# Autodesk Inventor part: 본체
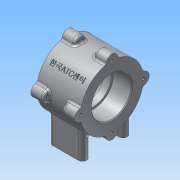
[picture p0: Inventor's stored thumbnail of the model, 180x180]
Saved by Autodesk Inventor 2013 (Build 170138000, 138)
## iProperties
Created: 2015-03
Part Number: 본체
Material: 알루미늄 6061
Document SubType Name: Modeling
Designer: Administrator
Density: 2.71 g/cm^3
Mass: 450.744 g
Surface Area: 332.371 cm^2
Volume: 166.326 cm^3
Author: Administrator
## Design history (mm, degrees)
sketch "스케치1"
  geometry: C1 r 37 at (0, 0); 1 further point
  constraints: 1 centre point, 1 coincident
  dimensions: "d0" = 74 diameter of C1
extrude "돌출1" new body sketch "스케치1" stored distance "d1" = 52; taper "d2" = 0 deg
sketch "스케치2"
  geometry: L1 (0, 0)-(0, 37); A1 r 37 centre (0, 0) between (0, 37) and (6.969, 36.338) reference; A2 r 7 centre (0, 37) between (6.969, 36.338) and (-6.969, 36.338)
  constraints: 5 point on circle, 2 end point, 1 centre point, 1 coincident, 1 vertical
  dimensions: "d4" = 14 diameter of A2
extrude "돌출2" join sketch "스케치2" distance "d5" = 15; taper "d6" = 0 deg
hole "구멍1" diameter "d12" = 42; stored, may be unused: countersink angle "d16" = 90 deg, drill point angle "d18" = 0 deg; dims "d10" = 10, "d11" = 10, "d13" = 6, "d14" = 47, "d15" = 22, "d17" = 8
chamfer "모따기1" distance "d19" = 1; stored, may be unused: second distance "d20" = 2, angle "d21" = 45 deg
fillet "모깎기1" dims "d22" = 0.3
fillet "모깎기2" dims "d23" = 3
fillet "모깎기3" dims "d24" = 3
sketch "스케치3"
  geometry: A1 r 7 centre (-37, 0) between (-38.239, 6.889) and (-38.239, -6.889) reference; A2 r 7 centre (0, -37) between (-6.889, -38.239) and (6.889, -38.239) reference; A3 r 7 centre (37, 0) between (38.239, -6.889) and (38.239, 6.889) reference; A4 r 7 centre (0, 37) between (6.889, 38.239) and (-6.889, 38.239) reference; 4 further points
  constraints: 4 coincident
hole "구멍2" sketch "스케치3" at (0, 37), (-37, 0), (37, 0), (0, -37) diameter "d25" = 3.242; stored, may be unused: countersink angle "d29" = 90 deg, drill point angle "d31" = 118 deg; dims "d26" = 8, "d27" = 47, "d28" = 22, "d30" = 11
sketch "스케치4"
  geometry: A1 r 7 centre (-37, 0) between (-38.239, 6.889) and (-38.239, -6.889) reference; A2 r 7 centre (0, -37) between (-6.889, -38.239) and (6.889, -38.239) reference; A3 r 7 centre (37, 0) between (38.239, -6.889) and (38.239, 6.889) reference; A4 r 7 centre (0, 37) between (6.889, 38.239) and (-6.889, 38.239) reference; 4 further points
  constraints: 4 coincident
hole "구멍3" sketch "스케치4" at (0, 37), (-37, 0), (0, -37), (37, 0) diameter "d32" = 3.242; stored, may be unused: countersink angle "d36" = 90 deg, drill point angle "d38" = 118 deg; dims "d33" = 8, "d34" = 47, "d35" = 22, "d37" = 11
node "작업 평면2"
  node "작업 평면1"
sketch "스케치5"
  geometry: 2 further points
  constraints: 1 coincident, 1 other
feature "엠보싱1" sketch "스케치5" dims "d41" = 0.5, "d42" = 0
node "작업 평면3"
sketch "스케치6"
  geometry: L1 (-29, 15)-(-29, -15); L2 (-19, -15)-(-19, 15); A1 r 5 centre (-24, -15) between (-29, -15) and (-19, -15); A2 r 5 centre (-24, 15) between (-19, 15) and (-29, 15); 2 further points
  constraints: 4 end point, 4 point on circle, 4 tangent, 2 centre point, 1 horizontal alignment, 1 midpoint, 1 parallel, 1 vertical
  dimensions: "d44" = 40 dimension on A1 A2; "d46" = 5 radius of A2; "d47" = 24 horizontal distance of A1.centre point (0, 0)
extrude "돌출3" join sketch "스케치6" stored distance "d48" = 15; taper "d49" = 0 deg
sketch "스케치7"
  geometry: L1 (-29, -15)-(-29, 15) reference; L2 (-19, 15)-(-19, -15) reference; L3 (29, 15)-(29, -15) reference; L4 (19, -15)-(19, 15) reference; A1 r 5 centre (-24, 15) between (-19, 15) and (-29, 15) reference; A2 r 5 centre (-24, -15) between (-29, -15) and (-19, -15) reference; A3 r 5 centre (24, -15) between (19, -15) and (29, -15) reference; A4 r 5 centre (24, 15) between (29, 15) and (19, 15) reference; 5 further points
  constraints: 4 coincident
hole "구멍4" sketch "스케치7" at (-24, 15), (-24, -15), (24, -15), (24, 15) diameter "d50" = 4.134; stored, may be unused: countersink angle "d54" = 90 deg, drill point angle "d56" = 118 deg; dims "d51" = 6, "d52" = 47, "d53" = 22, "d55" = 8
fillet "모깎기4" dims "d57" = 3
node "솔리드1"
pattern_circular "원형 패턴1" dims angle "d8" = 360 deg
mirror "대칭1"
mirror "대칭2"
mirror "대칭3"
node "절단 모서리 투영1"
other parameters: "d39" = 45 deg, "d40" = 84, "d43" = -56
